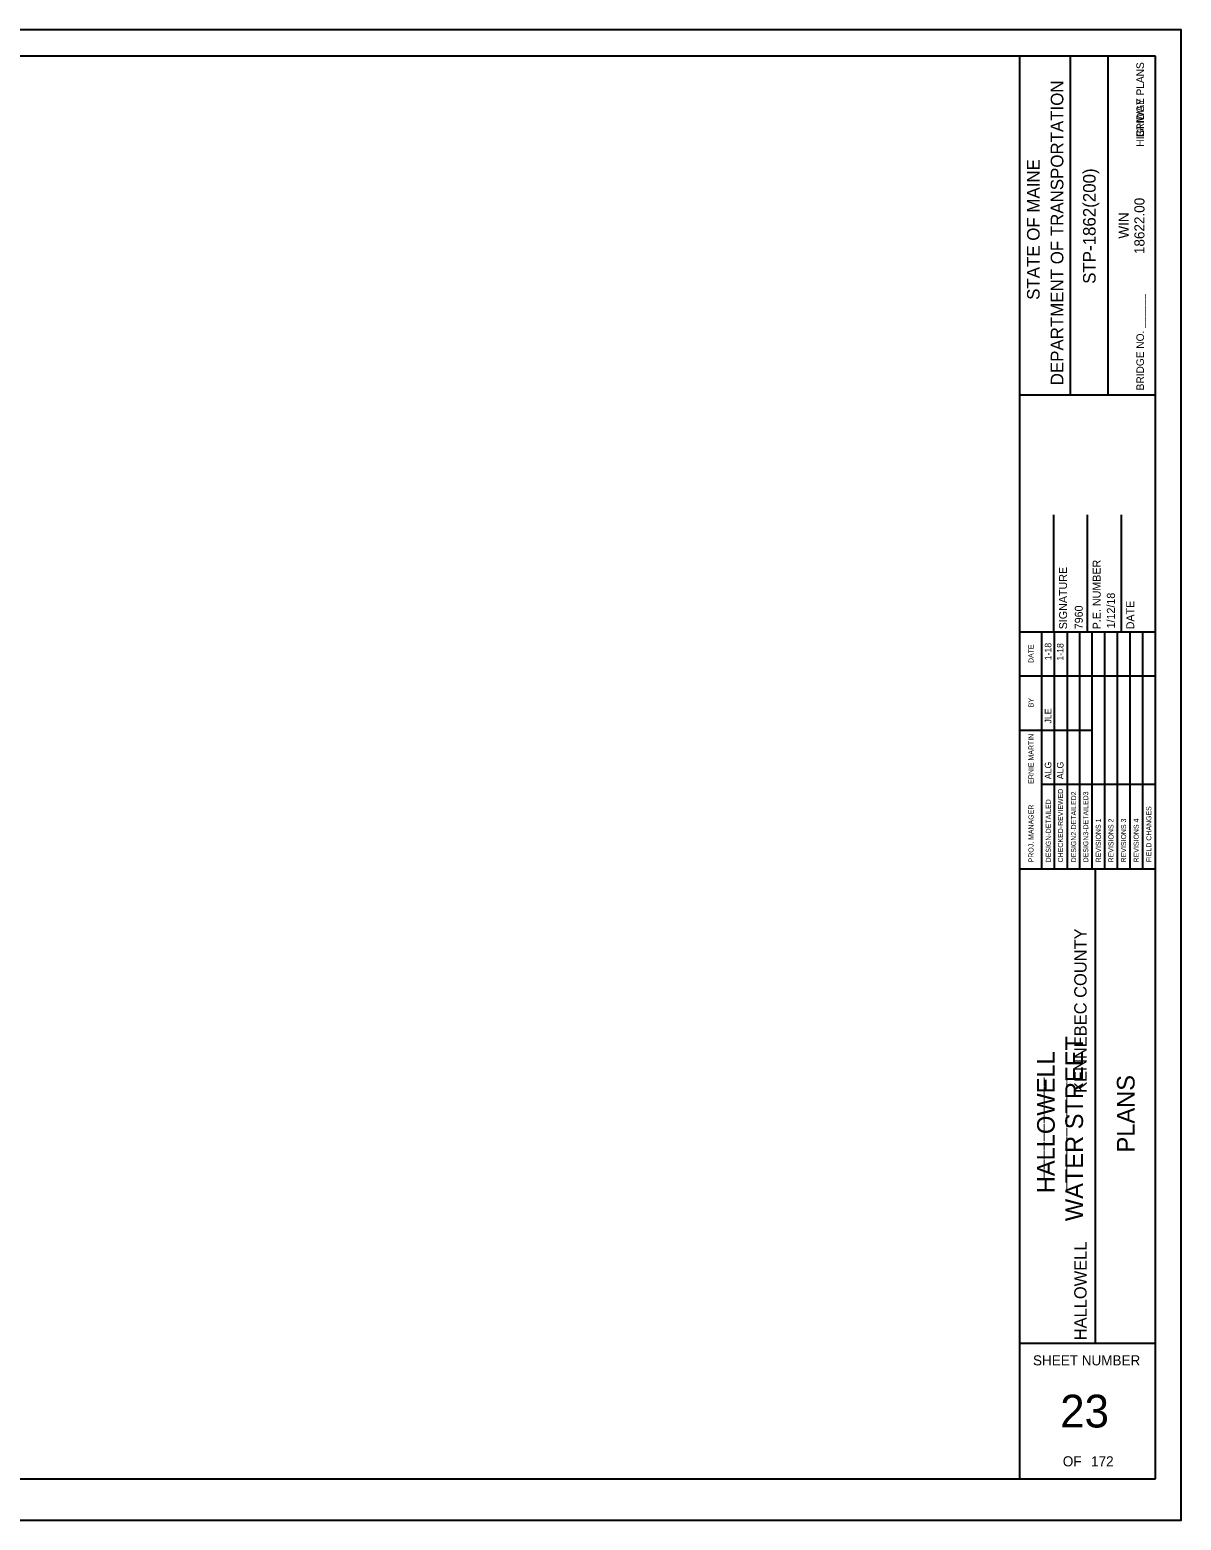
# Model space of a CAD drawing. Extents: x 0 to 850, y 0 to 550.
# Drawn here: x 425 to 850, y 0 to 550 of the extents above; entities that cross this region are included whole.
import ezdxf

# ---------------------------------------------------------------- set-up
doc = ezdxf.new("R2010")
doc.units = 0
for name, color, linetype in [('BORDER', 7, 'Continuous'), ('BRIDGE_TITLE', 7, 'Continuous'), ('Default', 7, 'Continuous'), ('HIGHWAY_TITLE', 7, 'Continuous'), ('PLOT BOUNDARY', 7, 'Continuous')]:
    doc.layers.add(name, color=color, linetype=linetype)

msp = doc.modelspace()

# ---------------------------------------------------------------- linework, layer by layer
at = {"layer": 'BORDER'}
for p, q in [((840.33, 540.24), (40.33, 540.24)), ((790.33, 15.26), (790.33, 540.26)), ((808.97, 415.23), (808.97, 540.23)), ((822.95, 415.23), (822.95, 540.23)), ((840.33, 15.26), (840.33, 540.26)), ((790.34, 415.22), (840.33, 415.22)), ((802.83, 327.76), (802.83, 371)), ((815.33, 327.76), (815.33, 371)), ((827.83, 327.76), (827.83, 371)), ((790.33, 327.76), (840.33, 327.76)), ((790.33, 240.26), (840.33, 240.26)), ((818.29, 65.26), (818.29, 240.26)), ((790.33, 65.26), (840.33, 65.26)), ((40.33, 15.24), (840.33, 15.24))]:
    msp.add_line(p, q, dxfattribs=at)
for points in [[(798.41, 311.51), (798.41, 327.76)], [(803.07, 240.27), (803.07, 327.76)], [(807.73, 327.76), (807.73, 240.27)], [(812.39, 240.27), (812.39, 327.76)], [(817.04, 240.27), (817.04, 327.76)], [(821.7, 240.27), (821.7, 327.76)], [(826.36, 240.27), (826.36, 327.76)], [(831.02, 240.27), (831.02, 327.76)], [(835.68, 240.27), (835.68, 327.76)], [(798.41, 240.27), (798.41, 324.23)], [(790.33, 311.51), (840.33, 311.51)], [(790.33, 291.51), (798.41, 291.51)], [(798.41, 291.51), (817.04, 291.51)], [(798.41, 271.51), (840.33, 271.51)]]:
    msp.add_lwpolyline(points, dxfattribs=at)
at = {"layer": 'Default'}
msp.add_lwpolyline([(40.33, 15.24), (790.33, 15.24), (790.33, 540.26), (40.33, 540.26)], close=True, dxfattribs=at)
at = {"layer": 'PLOT BOUNDARY'}
msp.add_lwpolyline([(-0.13, -0.05), (849.87, -0.05), (849.87, 549.95), (-0.13, 549.95)], close=True, dxfattribs=at)

# ---------------------------------------------------------------- texts
at = {"layer": 'BORDER'}
for s, height, p in [('DEPARTMENT OF TRANSPORTATION', 4.6588, (806.37, 418.77)), ('STATE OF MAINE', 4.6588, (797.61, 450.3)), ('STP-1862(200)', 4.6588, (818.29, 456.21)), ('18622.00', 3.726, (836.31, 467.18)), ('WIN', 3.726, (830.52, 472.89)), ('P.E. NUMBER', 2.9528, (820.14, 328.72)), ('SIGNATURE', 2.953, (807.73, 328.72)), ('1/12/18', 2.953, (825.38, 329.04)), ('7960', 2.953, (813.54, 328.72)), ('DATE', 2.953, (832.54, 328.72)), ('DATE', 1.857, (795.35, 316.29)), ('1-18', 2.423, (801.95, 317.25)), ('1-18', 2.423, (806.42, 317.14)), ('BY', 1.857, (795.35, 299.93)), ('JLE', 2.423, (801.95, 293.93)), ('ERNIE MARTIN', 1.8637, (795.35, 271.72)), ('ALG', 2.423, (801.95, 273.38)), ('ALG', 2.423, (806.42, 273.38)), ('DESIGN-DETAILED', 1.8637, (801.76, 242.7)), ('CHECKED-REVIEWED', 1.8637, (806.24, 242.7)), ('DESIGN2-DETAILED2', 1.8637, (811.08, 242.7)), ('DESIGN3-DETAILED3', 1.8637, (815.55, 242.7)), ('PROJ. MANAGER', 1.8637, (795.35, 242.7)), ('FIELD CHANGES', 1.8637, (838.85, 242.7)), ('REVISIONS 1', 1.8637, (820.21, 242.7)), ('REVISIONS 2', 1.8637, (824.87, 242.7)), ('REVISIONS 3', 1.8637, (829.53, 242.7)), ('REVISIONS 4', 1.8637, (834.19, 242.7)), ('PLANS', 6.521, (832.66, 135.64))]:
    msp.add_text(s, height=height, rotation=90, dxfattribs=at).set_placement(p)
for s, height, p in [('SHEET NUMBER', 3.7264, (795.16, 57.08)), ('23', 12.097, (805.21, 34.16)), ('OF', 3.726, (806.17, 19.81)), ('172', 3.726, (816.61, 19.81))]:
    msp.add_text(s, height=height, dxfattribs=at).set_placement(p)
at = {"layer": 'BRIDGE_TITLE'}
for s, height, p in [('BRIDGE PLANS', 2.795, (836.12, 510.37)), ('BRIDGE NO. ______', 2.795, (836.12, 416.9)), ('KENNEBEC COUNTY', 4.5358, (814.93, 157.65)), ('_____________', 4.5358, (806.55, 121.2)), ('___________', 4.5358, (798.16, 126.17)), ('HALLOWELL', 4.536, (814.93, 66.36))]:
    msp.add_text(s, height=height, rotation=90, dxfattribs=at).set_placement(p)
at = {"layer": 'HIGHWAY_TITLE'}
for s, height, p in [('HIGHWAY PLANS', 2.795, (836.12, 506.82)), ('WATER STREET', 6.5214, (813.63, 110.3)), ('HALLOWELL', 6.521, (803.19, 120.63))]:
    msp.add_text(s, height=height, rotation=90, dxfattribs=at).set_placement(p)

doc.saveas('drawing.dxf')
